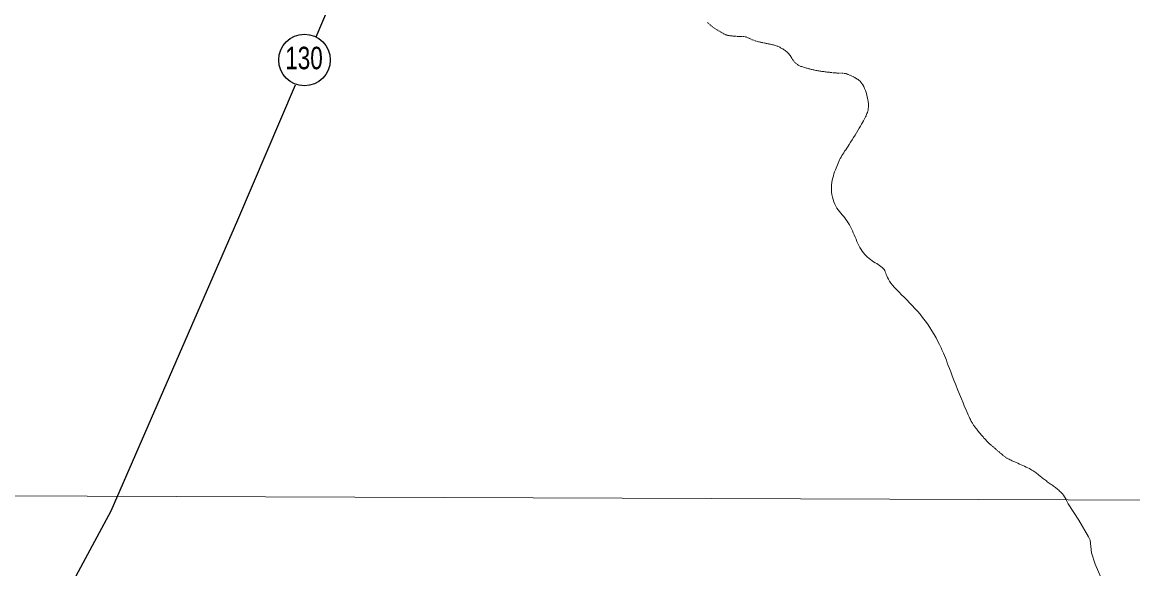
# Model space of a CAD drawing. Extents: x 553962 to 842807, y 8883888 to 9032388.
# Drawn here: x 600995 to 604455, y 8909688 to 8911389 of the extents above; entities that cross this region are included whole.
import ezdxf
from ezdxf.enums import TextEntityAlignment as Align

# ---------------------------------------------------------------- set-up
doc = ezdxf.new("R2010")
doc.units = 0
doc.header["$LTSCALE"] = 160
doc.layers.add('6', color=7, linetype='Continuous', lineweight=13)

msp = doc.modelspace()

# ---------------------------------------------------------------- linework, layer by layer
at = {"layer": '6'}
for p, q in [((603131, 8911387.2), (603129.6, 8911388.4)), ((603133.4, 8911385.2), (603132.3, 8911386.2)), ((603135.6, 8911383.3), (603134.6, 8911384.2)), ((603137.8, 8911381.3), (603136.7, 8911382.3)), ((603140, 8911379.3), (603138.9, 8911380.3)), ((603142.6, 8911377.2), (603141.3, 8911378.3)), ((603145.4, 8911374.9), (603144, 8911376.1)), ((603148.5, 8911372.6), (603147, 8911373.8)), ((603151.7, 8911370.4), (603150.1, 8911371.5)), ((603154.8, 8911368.4), (603153.2, 8911369.4)), ((603157.8, 8911366.6), (603156.3, 8911367.5)), ((603160.7, 8911364.9), (603159.2, 8911365.7)), ((603163.5, 8911363.3), (603162.1, 8911364.1)), ((603166.3, 8911361.7), (603164.9, 8911362.5)), ((603169, 8911360.1), (603167.6, 8911360.9)), ((603171.7, 8911358.5), (603170.3, 8911359.3)), ((603174.4, 8911356.9), (603173, 8911357.7)), ((603177, 8911355.3), (603175.7, 8911356.1)), ((603179.7, 8911353.8), (603178.3, 8911354.6)), ((603182.2, 8911352.4), (603180.9, 8911353.1)), ((603184.6, 8911351.1), (603183.4, 8911351.7)), ((603186.8, 8911350.1), (603185.8, 8911350.6)), ((603188.9, 8911349.3), (603187.9, 8911349.7)), ((603191, 8911348.7), (603190, 8911349)), ((603193.3, 8911348.2), (603192.2, 8911348.4)), ((603196, 8911347.7), (603194.6, 8911347.9)), ((603199.1, 8911347.2), (603197.5, 8911347.5)), ((603202.3, 8911346.8), (603200.7, 8911347)), ((603205.5, 8911346.4), (603203.9, 8911346.6)), ((603208.6, 8911346), (603207.1, 8911346.2)), ((603211.6, 8911345.7), (603210.1, 8911345.9)), ((603214.3, 8911345.5), (603213, 8911345.6)), ((603217, 8911345.3), (603215.6, 8911345.4)), ((603219.5, 8911345.2), (603218.2, 8911345.2)), ((603222, 8911345.1), (603220.8, 8911345.1)), ((603224.5, 8911345), (603223.2, 8911345.1)), ((603226.9, 8911345), (603225.7, 8911345)), ((603229.2, 8911345), (603228, 8911345)), ((603231.5, 8911345), (603230.3, 8911345)), ((603233.7, 8911344.9), (603232.6, 8911344.9)), ((603235.8, 8911344.9), (603234.8, 8911344.9)), ((603237.8, 8911344.9), (603236.8, 8911344.9)), ((603240.7, 8911344.8), (603239.7, 8911344.9)), ((603243.6, 8911344.6), (603242.6, 8911344.7)), ((603245.8, 8911344.2), (603244.7, 8911344.4)), ((603248, 8911343.7), (603246.9, 8911344)), ((603250.4, 8911343), (603249.2, 8911343.4)), ((603252.9, 8911342.1), (603251.6, 8911342.6)), ((603255.5, 8911341.1), (603254.2, 8911341.6)), ((603258.1, 8911339.9), (603256.8, 8911340.5)), ((603260.8, 8911338.7), (603259.4, 8911339.3)), ((603263.5, 8911337.3), (603262.1, 8911338)), ((603266.4, 8911336), (603265, 8911336.7)), ((603269.4, 8911334.6), (603267.9, 8911335.3)), ((603272.5, 8911333.3), (603271, 8911334)), ((603275.8, 8911332.1), (603274.1, 8911332.7)), ((603279.1, 8911330.9), (603277.4, 8911331.5)), ((603282.5, 8911329.9), (603280.8, 8911330.4)), ((603285.8, 8911329), (603284.2, 8911329.4)), ((603289.1, 8911328.2), (603287.5, 8911328.6)), ((603292.1, 8911327.5), (603290.6, 8911327.8)), ((603294.9, 8911326.9), (603293.5, 8911327.2)), ((603297.7, 8911326.3), (603296.3, 8911326.6)), ((603300.8, 8911325.7), (603299.2, 8911326)), ((603304.2, 8911325), (603302.5, 8911325.3)), ((603308.2, 8911324.2), (603306.2, 8911324.6)), ((603400, 8911266.3), (603398.8, 8911267.7)), ((603402.3, 8911263.8), (603401.2, 8911265)), ((603404.7, 8911261.5), (603403.5, 8911262.6)), ((603407.4, 8911259.2), (603406, 8911260.3)), ((603523.2, 8911231.6), (603521.3, 8911231.8)), ((603526.6, 8911231.3), (603524.9, 8911231.5)), ((603529.7, 8911231.1), (603528.2, 8911231.2)), ((603532.4, 8911231), (603531.1, 8911231.1)), ((603534.9, 8911230.9), (603533.7, 8911231)), ((603537.3, 8911230.9), (603536.1, 8911230.9)), ((603539.6, 8911230.9), (603538.5, 8911230.9)), ((603542.1, 8911230.8), (603540.8, 8911230.9)), ((603544.8, 8911230.7), (603543.4, 8911230.8)), ((603547.8, 8911230.5), (603546.2, 8911230.7)), ((603551.4, 8911230.2), (603549.6, 8911230.4)), ((603574.8, 8911223.6), (603573, 8911224.4)), ((603578.2, 8911222), (603576.5, 8911222.8)), ((603581.7, 8911220.4), (603580, 8911221.2)), ((604054.2, 8910038.5), (604052.7, 8910039.6)), ((604056.9, 8910036.4), (604055.5, 8910037.4)), ((604059.7, 8910034.4), (604058.2, 8910035.4)), ((576954.3, 8910001), (623612.7, 8909833))]:
    msp.add_line(p, q, dxfattribs=at)
at = {"layer": '6', "lineweight": 25}
for points in [[(601910.1, 8911344.1), (602223.7, 8912077.8), (602313.4, 8912293.8), (602321.9, 8912321.1), (602252.1, 8912505.5), (602217.1, 8912579.8), (602219.3, 8912630.5)], [(601054.1, 8909463.7), (601272.1, 8909867.7), (601666.5, 8910774.3), (601846, 8911194.3)]]:
    msp.add_lwpolyline(points, dxfattribs=at)
at = {"layer": '6'}
for points in [[(603397.7, 8911269.3), (603396.5, 8911271), (603395.2, 8911273), (603393.8, 8911275.2), (603392.4, 8911277.6), (603390.8, 8911280.1), (603389.2, 8911282.7), (603387.4, 8911285.3), (603385.5, 8911287.9), (603383.5, 8911290.4), (603381.4, 8911292.9), (603379.1, 8911295.2), (603376.7, 8911297.3), (603374.3, 8911299.2), (603371.8, 8911301.1), (603369.3, 8911302.8), (603366.8, 8911304.4), (603364.4, 8911305.9), (603362, 8911307.3), (603359.8, 8911308.6), (603357.7, 8911309.8), (603355.6, 8911311), (603353.5, 8911312.1), (603351.4, 8911313.1), (603349.1, 8911314.1), (603346.8, 8911315), (603344.3, 8911315.9), (603341.6, 8911316.8), (603338.7, 8911317.6), (603335.7, 8911318.3), (603332.7, 8911319), (603329.6, 8911319.7), (603326.5, 8911320.4), (603323.5, 8911321), (603320.6, 8911321.6), (603317.8, 8911322.2), (603315.2, 8911322.7), (603312.7, 8911323.2), (603310.4, 8911323.7), (603308.2, 8911324.2)], [(603412.3, 8911255.9), (603410.6, 8911257), (603408.9, 8911258.1)], [(603519.3, 8911232), (603517.2, 8911232.3), (603515, 8911232.5), (603512.6, 8911232.8), (603510.1, 8911233.1), (603507.5, 8911233.4), (603504.8, 8911233.7), (603501.9, 8911234.1), (603498.9, 8911234.4), (603495.9, 8911234.8), (603492.8, 8911235.2), (603489.6, 8911235.7), (603486.4, 8911236.1), (603483.2, 8911236.6), (603479.9, 8911237.1), (603476.7, 8911237.7), (603473.5, 8911238.2), (603470.3, 8911238.8), (603467.3, 8911239.3), (603464.3, 8911239.9), (603461.5, 8911240.5), (603458.7, 8911241.1), (603456.1, 8911241.7), (603453.6, 8911242.3), (603451.1, 8911242.9), (603448.6, 8911243.5), (603446.1, 8911244.2), (603443.5, 8911244.8), (603440.8, 8911245.6), (603438.1, 8911246.3), (603435.2, 8911247.2), (603432.3, 8911248), (603429.4, 8911248.9), (603426.5, 8911249.8), (603423.8, 8911250.8), (603421.1, 8911251.7), (603418.6, 8911252.8), (603416.3, 8911253.8), (603414.2, 8911254.8), (603412.3, 8911255.9)], [(603571.2, 8911225.2), (603569.3, 8911226), (603567.5, 8911226.7), (603565.6, 8911227.4), (603563.6, 8911228), (603561.6, 8911228.6), (603559.5, 8911229), (603557.4, 8911229.4), (603555.4, 8911229.7), (603553.4, 8911230)], [(603618, 8911086.3), (603620.1, 8911090.4), (603622, 8911094.2), (603623.8, 8911097.9), (603625.3, 8911101.4), (603626.8, 8911104.9), (603628.2, 8911108.4), (603629.3, 8911112.1), (603630.3, 8911116), (603631, 8911120.2), (603631.4, 8911124.8), (603631.4, 8911129.9), (603631.1, 8911135.5), (603630.4, 8911141.8), (603629.3, 8911148.5), (603627.9, 8911155.6), (603626.2, 8911162.7), (603624.1, 8911169.8), (603621.9, 8911176.7), (603619.4, 8911183.1), (603616.7, 8911188.9), (603613.9, 8911194.1), (603611, 8911198.5), (603608.1, 8911202.2), (603605.1, 8911205.4), (603602.1, 8911208.1), (603599.3, 8911210.4), (603596.5, 8911212.3), (603593.9, 8911213.9), (603591.5, 8911215.4), (603589.3, 8911216.6), (603587.2, 8911217.7), (603585.3, 8911218.7), (603583.5, 8911219.6)], [(603517.6, 8910852.6), (603516.6, 8910860.4), (603516, 8910868.2), (603515.9, 8910875.9), (603516.4, 8910883.3), (603517.3, 8910890.6), (603518.6, 8910897.6), (603520.2, 8910904.3), (603522, 8910910.9), (603524, 8910917.2), (603526.1, 8910923.3), (603528.3, 8910929.2), (603530.5, 8910934.9), (603532.6, 8910940.3), (603534.8, 8910945.6), (603536.9, 8910950.7), (603539.1, 8910955.6), (603541.4, 8910960.3), (603543.8, 8910964.9), (603546.2, 8910969.4), (603548.7, 8910973.8), (603551.4, 8910978.2), (603554.3, 8910982.6), (603557.3, 8910987.2), (603560.5, 8910992.1), (603564, 8910997.2), (603567.7, 8911002.8), (603571.6, 8911008.9), (603575.9, 8911015.5), (603580.4, 8911022.6), (603585, 8911030), (603589.6, 8911037.5), (603594.1, 8911045), (603598.5, 8911052.3), (603602.6, 8911059.3), (603606.5, 8911065.8), (603609.9, 8911071.7), (603612.9, 8911077), (603615.6, 8911081.8), (603618, 8911086.3)], [(603657.1, 8910637.5), (603652.4, 8910640.4), (603647.5, 8910643.4), (603642.7, 8910646.6), (603638, 8910650), (603633.3, 8910653.6), (603628.7, 8910657.4), (603624.2, 8910661.6), (603620, 8910666), (603615.9, 8910670.8), (603612, 8910676), (603608.4, 8910681.6), (603605, 8910687.5), (603601.8, 8910693.7), (603598.7, 8910700.1), (603595.7, 8910706.7), (603592.9, 8910713.4), (603590, 8910720.2), (603587.2, 8910726.8), (603584.3, 8910733.4), (603581.4, 8910739.9), (603578.4, 8910746.3), (603575.3, 8910752.4), (603572.1, 8910758.4), (603568.7, 8910764.2), (603565.2, 8910769.8), (603561.4, 8910775.1), (603557.5, 8910780.1), (603553.3, 8910785), (603549.1, 8910789.8), (603544.9, 8910794.7), (603540.8, 8910799.7), (603536.8, 8910804.9), (603533, 8910810.5), (603529.4, 8910816.5), (603526.3, 8910823), (603523.5, 8910830), (603521.1, 8910837.3), (603519.2, 8910844.9), (603517.6, 8910852.6)], [(603865.2, 8910358.8), (603861.6, 8910366.9), (603857.5, 8910375.8), (603852.8, 8910385.4), (603847.6, 8910395.6), (603841.9, 8910406.2), (603835.8, 8910417.1), (603829.3, 8910428), (603822.5, 8910438.9), (603815.3, 8910449.7), (603807.8, 8910460), (603800.1, 8910470), (603792.2, 8910479.8), (603784.1, 8910489.2), (603775.9, 8910498.3), (603767.6, 8910507.2), (603759.3, 8910515.9), (603751.1, 8910524.4), (603742.8, 8910532.7), (603734.8, 8910540.8), (603727.1, 8910548.7), (603719.7, 8910556.3), (603712.9, 8910563.6), (603706.8, 8910570.6), (603701.4, 8910577.2), (603696.9, 8910583.4), (603693.4, 8910589.2), (603690.7, 8910594.5), (603688.5, 8910599.5), (603686.8, 8910604.1), (603685.3, 8910608.4), (603683.8, 8910612.4), (603682, 8910616.1), (603679.9, 8910619.6), (603677.2, 8910622.8), (603673.9, 8910625.9), (603670.2, 8910628.9), (603666.1, 8910631.8), (603661.7, 8910634.6), (603657.1, 8910637.5)], [(603978.6, 8910109.9), (603976.6, 8910112.4), (603974.6, 8910114.9), (603972.6, 8910117.3), (603970.6, 8910119.8), (603968.7, 8910122.2), (603966.9, 8910124.5), (603965.1, 8910126.8), (603963.5, 8910128.9), (603961.9, 8910130.9), (603960.5, 8910132.9), (603959.1, 8910134.8), (603957.8, 8910136.7), (603956.5, 8910138.8), (603955.1, 8910140.9), (603953.8, 8910143.2), (603952.3, 8910145.8), (603950.8, 8910148.6), (603949.1, 8910152), (603947.1, 8910155.9), (603944.8, 8910160.8), (603942.2, 8910166.6), (603939.1, 8910173.7), (603935.4, 8910182.2), (603931.2, 8910192.3), (603926.3, 8910204.1), (603920.9, 8910217.2), (603915.1, 8910231.3), (603909.2, 8910245.8), (603903.4, 8910260.5), (603897.7, 8910274.8), (603892.4, 8910288.2), (603887.7, 8910300.5), (603883.6, 8910311.2), (603880.1, 8910320.7), (603877, 8910329.1), (603874.1, 8910336.7), (603871.2, 8910344.1), (603868.3, 8910351.3), (603865.2, 8910358.8)], [(604051.2, 8910040.8), (604049.5, 8910042.2), (604047.8, 8910043.5), (604046, 8910045), (604044.1, 8910046.5), (604042.3, 8910048), (604040.4, 8910049.6), (604038.6, 8910051.2), (604036.8, 8910052.7), (604035, 8910054.3), (604033.3, 8910055.9), (604031.6, 8910057.4), (604029.9, 8910058.9), (604028.3, 8910060.4), (604026.7, 8910061.8), (604025.1, 8910063.2), (604023.6, 8910064.5), (604022.1, 8910065.8), (604020.5, 8910067.1), (604019, 8910068.4), (604017.3, 8910069.7), (604015.7, 8910071.1), (604013.9, 8910072.7), (604012, 8910074.3), (604010, 8910076), (604007.9, 8910077.9), (604005.8, 8910079.9), (604003.5, 8910082), (604001.3, 8910084.1), (603999, 8910086.3), (603996.8, 8910088.6), (603994.6, 8910090.9), (603992.5, 8910093.2), (603990.4, 8910095.5), (603988.4, 8910097.9), (603986.4, 8910100.2), (603984.5, 8910102.6), (603982.5, 8910105), (603980.6, 8910107.4), (603978.6, 8910109.9)], [(604137, 8909997.1), (604132.8, 8909999.4), (604128.1, 8910001.8), (604123.1, 8910004.2), (604117.9, 8910006.6), (604112.6, 8910009), (604107.2, 8910011.4), (604101.8, 8910013.8), (604096.7, 8910016), (604091.8, 8910018.2), (604087.2, 8910020.2), (604083.1, 8910022.1), (604079.2, 8910023.9), (604075.8, 8910025.6), (604072.6, 8910027.2), (604069.8, 8910028.6), (604067.2, 8910029.9), (604065, 8910031.2), (604063, 8910032.3), (604061.3, 8910033.4)], [(604253.8, 8909889.8), (604249.8, 8909898.4), (604246.1, 8909905.6), (604242.5, 8909911.6), (604239.1, 8909916.6), (604235.9, 8909920.7), (604232.8, 8909924.1), (604229.9, 8909927), (604227, 8909929.5), (604224.3, 8909931.9), (604221.6, 8909934.2), (604219, 8909936.4), (604216.4, 8909938.5), (604213.8, 8909940.6), (604211.2, 8909942.6), (604208.5, 8909944.5), (604205.9, 8909946.5), (604203.1, 8909948.5), (604200.3, 8909950.5), (604197.4, 8909952.5), (604194.5, 8909954.6), (604191.6, 8909956.7), (604188.6, 8909958.8), (604185.7, 8909961), (604182.7, 8909963.2), (604179.7, 8909965.5), (604176.7, 8909967.8), (604173.7, 8909970.1), (604170.8, 8909972.5), (604167.8, 8909974.9), (604164.9, 8909977.2), (604162.1, 8909979.5), (604159.2, 8909981.8), (604156.4, 8909984), (604153.6, 8909986.2), (604150.7, 8909988.4), (604147.6, 8909990.5), (604144.3, 8909992.7), (604140.8, 8909994.9), (604137, 8909997.1)], [(604366.2, 8909638.2), (604338, 8909702), (604326.5, 8909737.2), (604322.2, 8909776.3), (604317.2, 8909786.9), (604287.3, 8909838.8), (604253.8, 8909889.8)]]:
    msp.add_lwpolyline(points, dxfattribs=at)
at = {"layer": '6', "lineweight": 25}
msp.add_circle((601874.1, 8911271.4), 80.3, dxfattribs=at)

# ---------------------------------------------------------------- texts
at = {"layer": '6', "width": 0.75}
msp.add_text('130', height=70, dxfattribs=at).set_placement((601872.6, 8911242.7), align=Align.CENTER)

doc.saveas('drawing.dxf')
